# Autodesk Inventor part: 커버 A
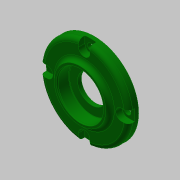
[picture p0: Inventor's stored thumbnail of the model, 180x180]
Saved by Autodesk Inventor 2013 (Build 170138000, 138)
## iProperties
Created: 2019-05
Part Number: 커버 A
Material: 알루미늄 6061
Document SubType Name: Modeling
Designer: mduedu
Density: 2.71 g/cm^3
Mass: 47.9863 g
Surface Area: 85.729 cm^2
Volume: 17.7071 cm^3
Author: mduedu
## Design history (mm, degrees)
sketch "스케치1"
  geometry: C1 r 31 at (0, 0); 1 further point
  constraints: 1 centre point, 1 coincident
  dimensions: "d0" = 62 diameter of C1
extrude "돌출1" new body sketch "스케치1" distance "d1" = 7; taper "d2" = 0 deg
sketch "스케치2"
  geometry: C1 r 18 at (0, 0); 1 further point
  constraints: 1 centre point, 1 coincident
  dimensions: "d3" = 36 diameter of C1
extrude "돌출2" join sketch "스케치2" distance "d4" = 3; taper "d5" = 0 deg
fillet "모깎기1" dims "d6" = 3
sketch "스케치3"
  geometry: C1 r 20 at (0, 0); 1 further point
  constraints: 1 centre point, 1 coincident
  dimensions: "d7" = 40 diameter of C1
extrude "돌출3" join sketch "스케치3" distance "d8" = 4; taper "d9" = 0 deg
sketch "스케치4"
  geometry: C1 r 17 at (0, 0); 1 further point
  constraints: 1 centre point, 1 coincident
  dimensions: "d10" = 34 diameter of C1
extrude "돌출4" cut sketch "스케치4" distance "d11" = 3; taper "d12" = 0 deg
sketch "스케치5"
  geometry: C1 r 16 at (0, 0); 1 further point
  constraints: 1 centre point, 1 coincident
  dimensions: "d13" = 32 diameter of C1
extrude "돌출5" cut sketch "스케치5" distance "d14" = 8.3; taper "d15" = 0 deg
sketch "스케치6"
  geometry: C1 r 10 at (0, 0); 1 further point
  constraints: 1 centre point, 1 coincident
  dimensions: "d16" = 20 diameter of C1
extrude "돌출6" cut sketch "스케치6" stored distance "d17" = 8.3; taper "d18" = 0 deg
fillet "모깎기2" dims "d19" = 0.3
fillet "모깎기3" dims "d20" = 3
fillet "모깎기4" dims "d21" = 3
chamfer "모따기1" distance "d22" = 1; stored, may be unused: second distance "d23" = 2, angle "d24" = 45 deg
sketch "스케치7" dims "d25" = 52
  geometry: L1 (-4, 26)-(-4, 30.741); L2 (4, 26)-(4, 30.741); A1 r 4 centre (0, 26) between (-4, 26) and (4, 26); A2 r 31 centre (0, 0) between (4, 30.741) and (-4, 30.741); 3 further points
  constraints: 4 end point, 4 point on circle, 2 centre point, 2 coincident, 2 tangent, 2 vertical alignment, 1 parallel, 1 vertical, 4 other
  dimensions: "d26" = 8 distance between parallel lines of L2 L1
extrude "돌출7" cut sketch "스케치7" distance "d27" = 4.4; taper "d28" = 0 deg
chamfer "모따기2" distance "d32" = 0.8; stored, may be unused: second distance "d33" = 2, angle "d34" = 30 deg
sketch "스케치8" dims "d36" = 52
  geometry: 6 further points
  constraints: 2 vertical alignment, 1 coincident, 7 other
  dimensions: "d39" = 360 deg dimension on point (0, 0) point (0, 26) (derived)
sketch "스케치9"
  geometry: 4 further points
  constraints: 4 other
hole "구멍1" sketch "스케치9" at (-26, 0), (0, -26), (26, 0), (0, 26) diameter "d41" = 4.5; stored, may be unused: countersink angle "d45" = 90 deg, drill point angle "d47" = 0 deg; dims "d42" = 6, "d43" = 4, "d44" = 2, "d46" = 8
node "솔리드1"
pattern_circular "원형 패턴1" dims angle "d30" = 360 deg
